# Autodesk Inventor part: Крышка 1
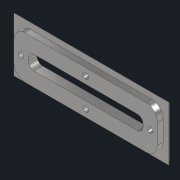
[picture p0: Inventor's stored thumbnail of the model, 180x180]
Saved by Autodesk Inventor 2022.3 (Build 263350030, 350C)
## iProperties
Created: 2022-08
Part Number: Крышка 1
Material: Сталь 40ХНМА
Document SubType Name: Modeling
Designer: Карташов
Density: 7.85 g/cm^3
Appearance: С умеренной полировкой
Author: Карташов
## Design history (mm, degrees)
sketch "Эскиз1"
  geometry: L1 (-27, -9.5)-(27, -9.5); L2 (27, -9.5)-(27, 9.5); L3 (27, 9.5)-(-27, 9.5); L4 (-27, 9.5)-(-27, -9.5); L5 (-27, -9.5)-(27, 9.5); L6 (27, -9.5)-(-27, 9.5); L7 (-18, -2.5)-(18, -2.5); L8 (20, -0.5)-(20, 0.5); L9 (18, 2.5)-(-18, 2.5); L10 (-20, 0.5)-(-20, -0.5); L11 (-20, -2.5)-(20, 2.5); L12 (20, -2.5)-(-20, 2.5); A1 r 2 centre (-18, 0.5) between (-18, 2.5) and (-20, 0.5); A2 r 2 centre (18, 0.5) between (20, 0.5) and (18, 2.5); A3 r 2 centre (18, -0.5) between (18, -2.5) and (20, -0.5); A4 r 2 centre (-18, -0.5) between (-20, -0.5) and (-18, -2.5); 1 further point
  constraints: 24 end point, 8 point on circle, 8 point on line, 8 tangent, 4 centre point, 4 midpoint, 4 parallel, 3 equal radius, 2 horizontal, 2 perpendicular
  dimensions: "d0" = 54 distance of L3.end L2.end; "d1" = 19 distance of L2.end L1.end; "d2" = 40 distance of L12.end L11.end; "d3" = 5 distance of L11.end L12.start; "d4" = 2 radius of A1 (derived)
extrude "Выдавливание1" new body sketch "Эскиз1" distance "d5" = 3; taper "d6" = 0 deg
sketch "Эскиз2"
  geometry: L1 (27, -9.5)-(27, 9.5) reference; L2 (27, 9.5)-(-27, 9.5) reference; L3 (-27, 9.5)-(-27, -9.5) reference; L4 (-27, -9.5)-(27, -9.5) reference; L5 (-20, -0.5)-(-20, 0.5) reference; L6 (-18, 2.5)-(18, 2.5) reference; L7 (20, 0.5)-(20, -0.5) reference; L8 (18, -2.5)-(-18, -2.5) reference; L9 (-21, -7.5)-(21, -7.5); L10 (25, -3.5)-(25, 3.5); L11 (21, 7.5)-(-21, 7.5); L12 (-25, 3.5)-(-25, -3.5); L13 (-25, -7.5)-(25, 7.5); L14 (25, -7.5)-(-25, 7.5); A1 r 2 centre (-18, -0.5) between (-20, -0.5) and (-18, -2.5) reference; A2 r 2 centre (-18, 0.5) between (-18, 2.5) and (-20, 0.5) reference; A3 r 2 centre (18, 0.5) between (20, 0.5) and (18, 2.5) reference; A4 r 2 centre (18, -0.5) between (18, -2.5) and (20, -0.5) reference; A5 r 4 centre (21, 3.5) between (25, 3.5) and (21, 7.5); A6 r 4 centre (21, -3.5) between (21, -7.5) and (25, -3.5); A7 r 4 centre (-21, -3.5) between (-25, -3.5) and (-21, -7.5); A8 r 4 centre (-21, 3.5) between (-21, 7.5) and (-25, 3.5); 1 further point
  constraints: 12 end point, 8 point on circle, 8 point on line, 8 tangent, 4 centre point, 3 equal radius, 2 midpoint, 2 parallel, 1 horizontal, 1 perpendicular
  dimensions: "d7" = 50 distance of L14.end L13.end; "d8" = 15 distance of L13.end L14.start; "d9" = 4 radius of A5
extrude "Выдавливание2" cut sketch "Эскиз2" distance "d10" = 2; taper "d11" = 0 deg
sketch "Эскиз3"
  geometry: L1 (-27, -9.5)-(-27, 9.5) reference; L2 (27, -9.5)-(-27, -9.5) reference; L3 (27, 9.5)-(27, -9.5) reference; L4 (-27, 9.5)-(27, 9.5) reference; L5 (-18, -2.5)-(18, -2.5) reference; L6 (-20, 0.5)-(-20, -0.5) reference; L7 (18, 2.5)-(-18, 2.5) reference; L8 (20, -0.5)-(20, 0.5) reference; L9 (0, -1.177)-(0, 0); L10 (0, 0)-(0.979, 0); A1 r 2 centre (18, -0.5) between (18, -2.5) and (20, -0.5) reference; A2 r 2 centre (-18, -0.5) between (-20, -0.5) and (-18, -2.5) reference; A3 r 2 centre (-18, 0.5) between (-18, 2.5) and (-20, 0.5) reference; A4 r 2 centre (18, 0.5) between (20, 0.5) and (18, 2.5) reference; 6 further points
  constraints: 4 end point, 2 midpoint, 2 symmetric about line, 1 horizontal alignment, 1 perpendicular, 1 vertical, 1 vertical alignment
  dimensions: "d12" = 5 distance of L9.end point (0, -5); "d13" = 22.5 distance of L9.end point (22.5, 0)
hole "Отверстие1" sketch "Эскиз3" at (0, -5), (22.5, 0), (-22.5, 0), (0, 5) diameter "d14" = 2; stored, may be unused: countersink angle "d18" = 90 deg, drill point angle "d20" = 0 deg; dims "d15" = 6, "d16" = 4, "d17" = 1, "d19" = 22.5
fillet "Сопряжение1" dims "d21" = 2
node "Твердое тело1"
node "Спроецированная петля1"
node "Спроецированная петля2"
